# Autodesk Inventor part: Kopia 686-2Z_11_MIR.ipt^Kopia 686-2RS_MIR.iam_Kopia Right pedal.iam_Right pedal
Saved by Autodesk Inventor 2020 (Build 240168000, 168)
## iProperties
Created: 2017-10
Part Number: Kopia 686-2Z_11_MIR.ipt^Kopia 686-2RS_MIR.iam_Kopia Right pedal.iam_Right pedal
Material: Ogólny
Document SubType Name: Modeling
Designer: Tomasz
Density: 1 g/cm^3
Appearance: Domyślna
Sending System: SolidWorks 2017
Last Author: Tomasz
Last Saved: 2017-10-01
Author: Tomasz
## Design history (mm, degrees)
